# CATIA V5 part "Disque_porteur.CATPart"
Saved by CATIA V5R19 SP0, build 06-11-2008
Part number: Disque_porteur
Bounding box of the stored display mesh (mm): x -149.973 to 149.973, y -149.973 to 149.973, z -25 to 15
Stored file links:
  G:\EU_thinkMotion\CFAO_2010\MMS_groupe1\MMS_groupe1\OK\vduret\vduret\CATIA\Disque_porteur.CATPart
  F:\CFAO TP\Machine_de_coupe.CATProduct
  G:\EU_thinkMotion\CFAO_2010\MMS_groupe1\MMS_groupe1\OK\vduret\vduret\CATIA\Couronne_tranchante.CATPart
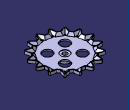
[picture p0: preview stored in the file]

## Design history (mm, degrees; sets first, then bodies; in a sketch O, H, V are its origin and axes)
Parameters
  Diam_ext_disque_porteur = 300 mm
  Diam_int_disque_porteur = 250 mm
  Epaisseur_disque_porteur = 15 mm
  Longueur_moyeu = 40 mm
  Diam_moyeu = 60 mm
  Longueur_epaulement = 100 mm
  Angle_beta = 55 deg
  Largeur_alesage = 22 mm
  Diam_trou_x4 = 50 mm
  Nbre_dents = 16
Body1 (main body)
  Sketch1 "Esquisse.1" on yz-plane, origin (0, 0, 0), H (0, 1, 0), V (0, 0, 1)
    line L1 (-125, 15) -> (0, 15)
    line L2 (-125, 0) -> (-125, 15)
    line L3 (0, -25) -> (-30, -25)
    line L4 (-30, -25) -> (-30, -4)
    line L5 (-100, -4) -> (-100, 0)
    line L6 (-100, 0) -> (-125, 0)
    line L7 (-30, -4) -> (-100, -4)
    axis line L8 (0, -65.5576) -> (0, 74.4424)
    point P7 (0, -65.5576)
    point P9 (0, 15)
    point P10 (0, -25)
    length L2 = 15 {= Epaisseur_disque_porteur}
    distance V L2 = 125 {= Diam_int_disque_porteur /2}
    distance L4 V = 30 {= Diam_moyeu /2}
    distance L1 L3 = 40 {= Longueur_moyeu}
    length L5 = 4
    distance L5 L8 = 100 {= Longueur_epaulement}
    horizontal: L1 H, L3 H, L6 H, L7 H
    vertical: L2 V, L4 V, L5 V, L8 V
    coincidence: P7 V, L8 P9, L8 P10, L6 H
  Shaft1: profile Sketch1, axis Sketch1.L8, angle 360
  Sketch2 on face of Shaft1 from Sketch1.L1, origin (0, 0, 15), H (1, 0, 0), V (0, 1, 0)
    arc A1 centre (0, 0) radius 125 from (17.1321, 123.8204) to (-17.1321, 123.8204) ccw
    reference projected circle E1 centre (0, 0) radius 125 from edge [face of Shaft1 from Sketch1.L2 | face of Shaft1 from Sketch1.L1]
    arc A2 centre (0, 0) radius 150 from (2.8503, 149.9729) to (-2.8503, 149.9729) ccw
    arc A3 centre (103.3526, 75) radius 130 from (-2.8503, 149.9729) to (-17.1321, 123.8204) ccw
    point P1 (103.3526, 75)
    construction line L1 (0, 310) -> (0, -169.7619)
    point P2 (0, 310)
    point P4 (-103.3526, 75)
    construction line L2 (-82.2496, 0) -> (0, 158)
    point P5 (0, 158)
    point P6 (-82.2496, 0)
    construction line L3 (0, 158) -> (82.2496, 0)
    point P7 (82.2496, 0)
    axis line L4 (-140, 150) -> (150, 150)
    arc A4 centre (-103.3526, 75) radius 130 from (17.1321, 123.8204) to (2.8503, 149.9729) ccw
    radius A2 = 150 {= Diam_ext_disque_porteur /2}
    radius A1 = 125 {= Diam_int_disque_porteur /2}
    distance P4 H = 75 {= Diam_ext_disque_porteur /4}
    distance P1 H = 75 {= Diam_ext_disque_porteur /4}
    angle L2 L3 = 55 {= Angle_beta}
    angle L2 L1 = 27.5 {= Angle_beta /2}
    distance P5 L4 = 8
    distance P4 A4 = 130
    distance P1 L2 = 130
    concentricity: A1 E1
    coincidence: P2 V, P5 L1, P7 H, P6 H
    vertical: L1 V
    tangency: A3 L2, L4 A2, A4 L3
    horizontal: L4 H
  Pad1: profile Sketch2, direction (0, 0, -1), length 15 {= Epaisseur_disque_porteur}
  Point1: type OnPlane, Support face of Pad1, H 0, V 0, Direction (1, 0, 0)
  Line1: type Normal, RefPoint Point1, RefSkin face of Pad1, Start -20, End 20
  CircPattern1: of Pad1, instances 16 {= Nbre_dents}, angular step 22.5 {= 360.0*1 deg/CircPattern1.AngularNumber}, axis from Line1
  Shell1: IntOffset 3, Face face of Pad1, ExtOffset 0
  Align1: SplitPlane face of Shell1, SewingRemoveFace face of Shell1
  Align2: SplitPlane face of Shell1, SewingRemoveFace face of Shell1
  Align3: SplitPlane face of Shell1, SewingRemoveFace face of Shell1
  Chamfer1: length 12, angle 45, on face of Align3
  Sketch3 on face of Shaft1 from Sketch1.L3, origin (0, 0, -25), H (1, 0, 0), V (0, -1, 0)
    point P1 (0, 0)
    point P2 (11, -6.3509)
    point P3 (11, 6.3509)
    point P4 (0, 12.7017)
    point P5 (-11, 6.3509)
    point P6 (-11, -6.3509)
    point P7 (0, -12.7017)
    point P8 (11, 0)
    line L1 (11, -6.3509) -> (11, 6.3509)
    line L2 (11, 6.3509) -> (0, 12.7017)
    line L3 (0, 12.7017) -> (-11, 6.3509)
    line L4 (-11, 6.3509) -> (-11, -6.3509)
    line L5 (-11, -6.3509) -> (0, -12.7017)
    line L6 (0, -12.7017) -> (11, -6.3509)
    construction line L7 (0, 0) -> (11, 0)
    construction circle A1 centre (0, 0) radius 12.7017
    construction arc A2 centre (-11, -6.3509) radius 12.7017 from (-11, 6.3509) to (0, -12.7017) cw
    construction arc A3 centre (11, 6.3509) radius 12.7017 from (0, 12.7017) to (11, -6.3509) ccw
    distance L1 L4 = 22 {= Largeur_alesage}
    distance L4 V = 11 {= Largeur_alesage /2}
    horizontal: L7 H
    coincidence: A1 P2, A1 P3, A1 P4, A1 P5, A1 P6, A1 P7, A2 P1, A3 P1, H P1
    midpoint: P8 L1
  Pocket1: profile Sketch3, direction (0, 0, 1), through (limit type 3)
  Sketch4 on face of Shaft1 from Sketch1.L3, origin (0, 0, -25), H (1, 0, 0), V (0, -1, 0)
    circle A1 centre (0, 0) radius 23
    radius A1 = 23 {= Diam_moyeu /2-7mm}
  Pocket2: profile Sketch4, direction (0, 0, 1), length 2
  Sketch5 on face of Shell1, origin (0, 0, 3), H (1, 0, 0), V (0, 1, 0)
    circle A1 centre (0, 0) radius 23
    radius A1 = 23 {= Diam_moyeu /2-7mm}
  Pocket3: profile Sketch5, direction (0, 0, -1), length 2
  Point2: type OnPlane, Support face of Align3, H 0, V 115 {= Diam_int_disque_porteur /2-10mm}, Direction (1, 0, 0)
  Sketch6 on face of Shell1, origin (0, 115, 3), H (1, 0, 0), V (0, 1, 0)
    point P1 (0, 0)
    reference projected point E1 (0, 0) from Point2
    coincidence: E1 P1
  Hole1: placed by Sketch6, at (0, 115, 3) direction (0, 0, -1), diameter 6, through (limit type 3)
  CircPattern2: of Hole1, instances 16 {= Nbre_dents}, angular step 22.5 {= 360.0*1 deg/CircPattern2.AngularNumber}, axis from Line1
  Sketch7 on yz-plane, origin (0, 0, 0), H (0, 1, 0), V (0, 0, 1)
    line L1 (30, -4) -> (30, -25)
    point P2 (30, -25)
    line L2 (30, -25) -> (100, -4)
    line L3 (100, -4) -> (30, -4)
    reference projected line E1 (-80, -4) -> (80, -4) from edge [face of Shaft1 from Sketch1.L7 | face of Shaft1 from Sketch1.L5]
    reference projected line E2 (-30, -25) -> (30, -25) from edge [face of Shaft1 from Sketch1.L3 | face of Shaft1 from Sketch1.L4]
    length L3 = 70 {= Longueur_epaulement -Diam_moyeu /2}
    distance L1 V = 30 {= Diam_moyeu /2}
    vertical: L1 V
    horizontal: L3 H
    coincidence: L3 E1, P2 E2
  Sketch8 on face of Shell1, origin (0, 0, 3), H (1, 0, 0), V (0, 1, 0)
    line L1 (2, 28) -> (-2, 28)
    point P2 (-2, 28)
    line L2 (-2, 28) -> (-1, 100)
    point P3 (-1, 100)
    line L3 (-1, 100) -> (1, 100)
    line L4 (1, 100) -> (2, 28)
    reference projected circle E1 centre (0, 0) radius 100 from edge [face of Shaft1 from Sketch1.L7 | face of Shaft1 from Sketch1.L5]
    length L3 = 2
    length L1 = 4
    distance P2 V = 2
    distance P3 V = 1
    distance L1 H = 28 {= Diam_moyeu /2-2mm}
    horizontal: L1 H, L3 H
    tangency: L3 E1
  SolidCombine1: FirstComponentProfile Sketch7, FirstComponentDirection Sketch7, SecondComponentProfile Sketch8, SecondComponentDirection Sketch8
  CircPattern3: of SolidCombine1, instances 4, angular step 90 {= 360.0*1 deg/CircPattern3.AngularNumber}, axis from Line1
  Sketch9 on face of Shaft1 from Sketch1.L7, origin (0, 0, -4), H (1, 0, 0), V (0, -1, 0)
    circle A1 centre (45.9619, 45.9619) radius 25
    point P1 (45.9619, 45.9619)
    reference projected point E1 (0, 0) from Point1
    axis line L1 (0, 0) -> (45.9619, 45.9619)
    radius A1 = 25 {= Diam_trou_x4 /2}
    distance P1 E1 = 65 {= Longueur_epaulement -Diam_trou_x4 /2-10mm}
    angle L1 H = 45
  Pocket4: profile Sketch9, direction (0, 0, 1), through (limit type 3)
  CircPattern4: of Pocket4, instances 4, angular step 90 {= 360.0*1 deg/CircPattern4.AngularNumber}, axis from Line1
